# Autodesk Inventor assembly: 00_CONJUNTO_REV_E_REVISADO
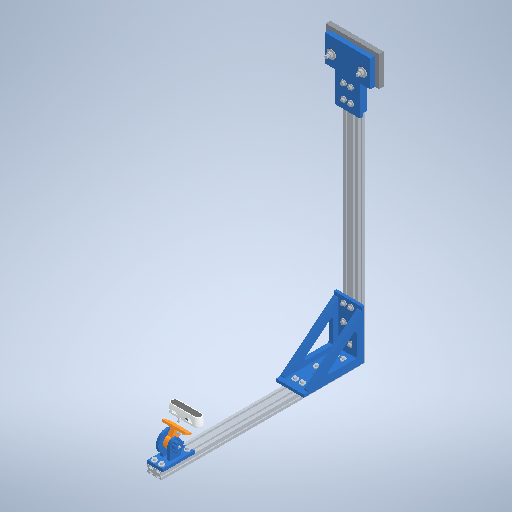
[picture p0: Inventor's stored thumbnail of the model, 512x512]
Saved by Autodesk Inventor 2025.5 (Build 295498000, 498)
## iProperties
Company: Open CASCADE
Created: 2026-10
Part Number: 00_CONJUNTO_REV_E_REVISADO
Description: Open CASCADE Model
Document SubType Name: Assembly
Designer: Luis M
Authority: Unknown
Sending System: Open CASCADE 7.9
Preprocessor: Open CASCADE STEP processor 7.9
Title: Open CASCADE Shape Model
Author: Author
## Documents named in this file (98)
- C:\Users\Luis M\Desktop\TESIS\CAD_TESIS\ACOPLE_CAMARA\ACOPLE_CAMARA.iam
- C:\Users\Luis M\Desktop\TESIS\CAD_TESIS\ACOPLE_CAMARA\IPT\COMPONENTES_IAM\perfil_horizontal_2040_700.ipt
- C:\Users\Luis M\Desktop\TESIS\CAD_TESIS\ACOPLE_CAMARA\IPT\COMPONENTES_IAM\perfil_vertical_2040_550.ipt
- C:\Users\Luis M\Desktop\TESIS\CAD_TESIS\ACOPLE_CAMARA\IPT\COMPONENTES_IAM\horquilla.ipt
- C:\Users\Luis M\Desktop\TESIS\CAD_TESIS\ACOPLE_CAMARA\IPT\COMPONENTES_IAM\placa_movil.ipt
- C:\Users\Luis M\Desktop\TESIS\CAD_TESIS\ACOPLE_CAMARA\IPT\COMPONENTES_IAM\pomo.ipt
- C:\Users\Luis M\Desktop\TESIS\CAD_TESIS\ACOPLE_CAMARA\IPT\COMPONENTES_IAM\adaptador_Jaco2_2040.ipt
- C:\Users\Luis M\Desktop\TESIS\CAD_TESIS\ACOPLE_CAMARA\IPT\COMPONENTES_IAM\base_Jaco2_BANDA_LOCAL_REFERENCIA.ipt
- C:\Users\Luis M\Desktop\TESIS\CAD_TESIS\ACOPLE_CAMARA\IPT\COMPONENTES_IAM\contraplaca_ACERO_1_5mm.ipt
- C:\Users\Luis M\Desktop\TESIS\CAD_TESIS\ACOPLE_CAMARA\IPT\COMPONENTES_IAM\pivote_M5x40.ipt
- C:\Users\Luis M\Desktop\TESIS\CAD_TESIS\ACOPLE_CAMARA\IPT\COMPONENTES_IAM\arandela_M5_-14.3.ipt
- C:\Users\Luis M\Desktop\TESIS\CAD_TESIS\ACOPLE_CAMARA\IPT\COMPONENTES_IAM\arandela_M5_13.3.ipt
- C:\Users\Luis M\Desktop\TESIS\CAD_TESIS\ACOPLE_CAMARA\IPT\COMPONENTES_IAM\tuerca_M5.ipt
- C:\Users\Luis M\Desktop\TESIS\CAD_TESIS\ACOPLE_CAMARA\IPT\COMPONENTES_IAM\M3x8_camara_-22.5.ipt
- C:\Users\Luis M\Desktop\TESIS\CAD_TESIS\ACOPLE_CAMARA\IPT\COMPONENTES_IAM\arandela_M3_-22.5.ipt
- C:\Users\Luis M\Desktop\TESIS\CAD_TESIS\ACOPLE_CAMARA\IPT\COMPONENTES_IAM\M3x8_camara_22.5.ipt
- C:\Users\Luis M\Desktop\TESIS\CAD_TESIS\ACOPLE_CAMARA\IPT\COMPONENTES_IAM\arandela_M3_22.5.ipt
- C:\Users\Luis M\Desktop\TESIS\CAD_TESIS\ACOPLE_CAMARA\IPT\COMPONENTES_IAM\M5x16_horquilla_-10_-36.0.ipt
- C:\Users\Luis M\Desktop\TESIS\CAD_TESIS\ACOPLE_CAMARA\IPT\COMPONENTES_IAM\arandela2mm_horquilla_-10_-36.0.ipt
- C:\Users\Luis M\Desktop\TESIS\CAD_TESIS\ACOPLE_CAMARA\IPT\COMPONENTES_IAM\T_horquilla_-10_-36.0.ipt
- C:\Users\Luis M\Desktop\TESIS\CAD_TESIS\ACOPLE_CAMARA\IPT\COMPONENTES_IAM\M5x16_horquilla_-10_36.0.ipt
- C:\Users\Luis M\Desktop\TESIS\CAD_TESIS\ACOPLE_CAMARA\IPT\COMPONENTES_IAM\arandela2mm_horquilla_-10_36.0.ipt
- C:\Users\Luis M\Desktop\TESIS\CAD_TESIS\ACOPLE_CAMARA\IPT\COMPONENTES_IAM\T_horquilla_-10_36.0.ipt
- C:\Users\Luis M\Desktop\TESIS\CAD_TESIS\ACOPLE_CAMARA\IPT\COMPONENTES_IAM\M5x16_collar_-10_630.ipt
- C:\Users\Luis M\Desktop\TESIS\CAD_TESIS\ACOPLE_CAMARA\IPT\COMPONENTES_IAM\arandela2mm_collar_-10_630.ipt
- C:\Users\Luis M\Desktop\TESIS\CAD_TESIS\ACOPLE_CAMARA\IPT\COMPONENTES_IAM\T_collar_-10_630.ipt
- C:\Users\Luis M\Desktop\TESIS\CAD_TESIS\ACOPLE_CAMARA\IPT\COMPONENTES_IAM\M5x16_collar_-10_670.ipt
- C:\Users\Luis M\Desktop\TESIS\CAD_TESIS\ACOPLE_CAMARA\IPT\COMPONENTES_IAM\arandela2mm_collar_-10_670.ipt
- C:\Users\Luis M\Desktop\TESIS\CAD_TESIS\ACOPLE_CAMARA\IPT\COMPONENTES_IAM\T_collar_-10_670.ipt
- C:\Users\Luis M\Desktop\TESIS\CAD_TESIS\ACOPLE_CAMARA\IPT\COMPONENTES_IAM\M5x16_horquilla_10_-36.0.ipt
- C:\Users\Luis M\Desktop\TESIS\CAD_TESIS\ACOPLE_CAMARA\IPT\COMPONENTES_IAM\arandela2mm_horquilla_10_-36.0.ipt
- C:\Users\Luis M\Desktop\TESIS\CAD_TESIS\ACOPLE_CAMARA\IPT\COMPONENTES_IAM\T_horquilla_10_-36.0.ipt
- C:\Users\Luis M\Desktop\TESIS\CAD_TESIS\ACOPLE_CAMARA\IPT\COMPONENTES_IAM\M5x16_horquilla_10_36.0.ipt
- C:\Users\Luis M\Desktop\TESIS\CAD_TESIS\ACOPLE_CAMARA\IPT\COMPONENTES_IAM\arandela2mm_horquilla_10_36.0.ipt
- C:\Users\Luis M\Desktop\TESIS\CAD_TESIS\ACOPLE_CAMARA\IPT\COMPONENTES_IAM\T_horquilla_10_36.0.ipt
- C:\Users\Luis M\Desktop\TESIS\CAD_TESIS\ACOPLE_CAMARA\IPT\COMPONENTES_IAM\M5x16_collar_10_630.ipt
- C:\Users\Luis M\Desktop\TESIS\CAD_TESIS\ACOPLE_CAMARA\IPT\COMPONENTES_IAM\arandela2mm_collar_10_630.ipt
- C:\Users\Luis M\Desktop\TESIS\CAD_TESIS\ACOPLE_CAMARA\IPT\COMPONENTES_IAM\T_collar_10_630.ipt
- C:\Users\Luis M\Desktop\TESIS\CAD_TESIS\ACOPLE_CAMARA\IPT\COMPONENTES_IAM\M5x16_collar_10_670.ipt
- C:\Users\Luis M\Desktop\TESIS\CAD_TESIS\ACOPLE_CAMARA\IPT\COMPONENTES_IAM\arandela2mm_collar_10_670.ipt
- C:\Users\Luis M\Desktop\TESIS\CAD_TESIS\ACOPLE_CAMARA\IPT\COMPONENTES_IAM\T_collar_10_670.ipt
- C:\Users\Luis M\Desktop\TESIS\CAD_TESIS\ACOPLE_CAMARA\IPT\COMPONENTES_IAM\11_acople_triangulado_derecho.ipt
- C:\Users\Luis M\Desktop\TESIS\CAD_TESIS\ACOPLE_CAMARA\IPT\COMPONENTES_IAM\12_acople_triangulado_izquierdo.ipt
- C:\Users\Luis M\Desktop\TESIS\CAD_TESIS\ACOPLE_CAMARA\IPT\COMPONENTES_IAM\M5x16_acople_v_-10_50.0.ipt
- C:\Users\Luis M\Desktop\TESIS\CAD_TESIS\ACOPLE_CAMARA\IPT\COMPONENTES_IAM\arandela_acople_v_-10_50.0.ipt
- C:\Users\Luis M\Desktop\TESIS\CAD_TESIS\ACOPLE_CAMARA\IPT\COMPONENTES_IAM\T_acople_v_-10_50.0.ipt
- C:\Users\Luis M\Desktop\TESIS\CAD_TESIS\ACOPLE_CAMARA\IPT\COMPONENTES_IAM\M5x16_acople_v_-10_105.0.ipt
- C:\Users\Luis M\Desktop\TESIS\CAD_TESIS\ACOPLE_CAMARA\IPT\COMPONENTES_IAM\arandela_acople_v_-10_105.0.ipt
- C:\Users\Luis M\Desktop\TESIS\CAD_TESIS\ACOPLE_CAMARA\IPT\COMPONENTES_IAM\T_acople_v_-10_105.0.ipt
- C:\Users\Luis M\Desktop\TESIS\CAD_TESIS\ACOPLE_CAMARA\IPT\COMPONENTES_IAM\M5x16_acople_v_-10_165.0.ipt
- C:\Users\Luis M\Desktop\TESIS\CAD_TESIS\ACOPLE_CAMARA\IPT\COMPONENTES_IAM\arandela_acople_v_-10_165.0.ipt
- C:\Users\Luis M\Desktop\TESIS\CAD_TESIS\ACOPLE_CAMARA\IPT\COMPONENTES_IAM\T_acople_v_-10_165.0.ipt
- C:\Users\Luis M\Desktop\TESIS\CAD_TESIS\ACOPLE_CAMARA\IPT\COMPONENTES_IAM\M5x16_acople_h_-10_45.0.ipt
- C:\Users\Luis M\Desktop\TESIS\CAD_TESIS\ACOPLE_CAMARA\IPT\COMPONENTES_IAM\arandela_acople_h_-10_45.0.ipt
- C:\Users\Luis M\Desktop\TESIS\CAD_TESIS\ACOPLE_CAMARA\IPT\COMPONENTES_IAM\T_acople_h_-10_45.0.ipt
- C:\Users\Luis M\Desktop\TESIS\CAD_TESIS\ACOPLE_CAMARA\IPT\COMPONENTES_IAM\M5x16_acople_h_-10_90.0.ipt
- C:\Users\Luis M\Desktop\TESIS\CAD_TESIS\ACOPLE_CAMARA\IPT\COMPONENTES_IAM\arandela_acople_h_-10_90.0.ipt
- C:\Users\Luis M\Desktop\TESIS\CAD_TESIS\ACOPLE_CAMARA\IPT\COMPONENTES_IAM\T_acople_h_-10_90.0.ipt
- C:\Users\Luis M\Desktop\TESIS\CAD_TESIS\ACOPLE_CAMARA\IPT\COMPONENTES_IAM\M5x16_acople_h_-10_135.0.ipt
- C:\Users\Luis M\Desktop\TESIS\CAD_TESIS\ACOPLE_CAMARA\IPT\COMPONENTES_IAM\arandela_acople_h_-10_135.0.ipt
- C:\Users\Luis M\Desktop\TESIS\CAD_TESIS\ACOPLE_CAMARA\IPT\COMPONENTES_IAM\T_acople_h_-10_135.0.ipt
- C:\Users\Luis M\Desktop\TESIS\CAD_TESIS\ACOPLE_CAMARA\IPT\COMPONENTES_IAM\M5x16_acople_v_10_50.0.ipt
- C:\Users\Luis M\Desktop\TESIS\CAD_TESIS\ACOPLE_CAMARA\IPT\COMPONENTES_IAM\arandela_acople_v_10_50.0.ipt
- C:\Users\Luis M\Desktop\TESIS\CAD_TESIS\ACOPLE_CAMARA\IPT\COMPONENTES_IAM\T_acople_v_10_50.0.ipt
- C:\Users\Luis M\Desktop\TESIS\CAD_TESIS\ACOPLE_CAMARA\IPT\COMPONENTES_IAM\M5x16_acople_v_10_105.0.ipt
- C:\Users\Luis M\Desktop\TESIS\CAD_TESIS\ACOPLE_CAMARA\IPT\COMPONENTES_IAM\arandela_acople_v_10_105.0.ipt
- C:\Users\Luis M\Desktop\TESIS\CAD_TESIS\ACOPLE_CAMARA\IPT\COMPONENTES_IAM\T_acople_v_10_105.0.ipt
- C:\Users\Luis M\Desktop\TESIS\CAD_TESIS\ACOPLE_CAMARA\IPT\COMPONENTES_IAM\M5x16_acople_v_10_165.0.ipt
- C:\Users\Luis M\Desktop\TESIS\CAD_TESIS\ACOPLE_CAMARA\IPT\COMPONENTES_IAM\arandela_acople_v_10_165.0.ipt
- C:\Users\Luis M\Desktop\TESIS\CAD_TESIS\ACOPLE_CAMARA\IPT\COMPONENTES_IAM\T_acople_v_10_165.0.ipt
- C:\Users\Luis M\Desktop\TESIS\CAD_TESIS\ACOPLE_CAMARA\IPT\COMPONENTES_IAM\M5x16_acople_h_10_45.0.ipt
- C:\Users\Luis M\Desktop\TESIS\CAD_TESIS\ACOPLE_CAMARA\IPT\COMPONENTES_IAM\arandela_acople_h_10_45.0.ipt
- C:\Users\Luis M\Desktop\TESIS\CAD_TESIS\ACOPLE_CAMARA\IPT\COMPONENTES_IAM\T_acople_h_10_45.0.ipt
- C:\Users\Luis M\Desktop\TESIS\CAD_TESIS\ACOPLE_CAMARA\IPT\COMPONENTES_IAM\M5x16_acople_h_10_90.0.ipt
- C:\Users\Luis M\Desktop\TESIS\CAD_TESIS\ACOPLE_CAMARA\IPT\COMPONENTES_IAM\arandela_acople_h_10_90.0.ipt
- C:\Users\Luis M\Desktop\TESIS\CAD_TESIS\ACOPLE_CAMARA\IPT\COMPONENTES_IAM\T_acople_h_10_90.0.ipt
- C:\Users\Luis M\Desktop\TESIS\CAD_TESIS\ACOPLE_CAMARA\IPT\COMPONENTES_IAM\M5x16_acople_h_10_135.0.ipt
- C:\Users\Luis M\Desktop\TESIS\CAD_TESIS\ACOPLE_CAMARA\IPT\COMPONENTES_IAM\arandela_acople_h_10_135.0.ipt
- C:\Users\Luis M\Desktop\TESIS\CAD_TESIS\ACOPLE_CAMARA\IPT\COMPONENTES_IAM\T_acople_h_10_135.0.ipt
- C:\Users\Luis M\Desktop\TESIS\CAD_TESIS\ACOPLE_CAMARA\IPT\COMPONENTES_IAM\DIN7991_M8x45_-43.5.ipt
- C:\Users\Luis M\Desktop\TESIS\CAD_TESIS\ACOPLE_CAMARA\IPT\COMPONENTES_IAM\arandela_M8_24x2_-43.5_15.ipt
- C:\Users\Luis M\Desktop\TESIS\CAD_TESIS\ACOPLE_CAMARA\IPT\COMPONENTES_IAM\arandela_M8_24x2_-43.5_29.5.ipt
- C:\Users\Luis M\Desktop\TESIS\CAD_TESIS\ACOPLE_CAMARA\IPT\COMPONENTES_IAM\casquillo_METAL_L12_5_-43.5.ipt
- C:\Users\Luis M\Desktop\TESIS\CAD_TESIS\ACOPLE_CAMARA\IPT\COMPONENTES_IAM\anillo_SILICONA_precarga_-43.5.ipt
- C:\Users\Luis M\Desktop\TESIS\CAD_TESIS\ACOPLE_CAMARA\IPT\COMPONENTES_IAM\centrador_PLA_-43.5.ipt
- C:\Users\Luis M\Desktop\TESIS\CAD_TESIS\ACOPLE_CAMARA\IPT\COMPONENTES_IAM\tuerca_M8_regular_-43.5.ipt
- C:\Users\Luis M\Desktop\TESIS\CAD_TESIS\ACOPLE_CAMARA\IPT\COMPONENTES_IAM\DIN7991_M8x45_43.5.ipt
- C:\Users\Luis M\Desktop\TESIS\CAD_TESIS\ACOPLE_CAMARA\IPT\COMPONENTES_IAM\arandela_M8_24x2_43.5_15.ipt
- C:\Users\Luis M\Desktop\TESIS\CAD_TESIS\ACOPLE_CAMARA\IPT\COMPONENTES_IAM\arandela_M8_24x2_43.5_29.5.ipt
- C:\Users\Luis M\Desktop\TESIS\CAD_TESIS\ACOPLE_CAMARA\IPT\COMPONENTES_IAM\casquillo_METAL_L12_5_43.5.ipt
- C:\Users\Luis M\Desktop\TESIS\CAD_TESIS\ACOPLE_CAMARA\IPT\COMPONENTES_IAM\anillo_SILICONA_precarga_43.5.ipt
- C:\Users\Luis M\Desktop\TESIS\CAD_TESIS\ACOPLE_CAMARA\IPT\COMPONENTES_IAM\centrador_PLA_43.5.ipt
- C:\Users\Luis M\Desktop\TESIS\CAD_TESIS\ACOPLE_CAMARA\IPT\COMPONENTES_IAM\tuerca_M8_regular_43.5.ipt
- C:\Users\Luis M\Desktop\TESIS\CAD_TESIS\ACOPLE_CAMARA\IPT\COMPONENTES_IAM\bloqueo_M3x30.ipt
- C:\Users\Luis M\Desktop\TESIS\CAD_TESIS\ACOPLE_CAMARA\IPT\COMPONENTES_IAM\arandela_bloqueo_M3_-14.3.ipt
- C:\Users\Luis M\Desktop\TESIS\CAD_TESIS\ACOPLE_CAMARA\IPT\COMPONENTES_IAM\arandela_bloqueo_M3_6.0.ipt
- C:\Users\Luis M\Desktop\TESIS\CAD_TESIS\ACOPLE_CAMARA\IPT\COMPONENTES_IAM\tuerca_bloqueo_M3_Nyloc.ipt
- C:\Users\Luis M\Desktop\TESIS\CAD_TESIS\ACOPLE_CAMARA\INTEL_REALSENSE_D435I.ipt
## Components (97 placed, 97 different names)
1. Perfil V-Slot 2040 x 700 mm - horizontal (referencia)
2. Perfil V-Slot 2040 x 550 mm - vertical (referencia)
3. horquilla_3
4. placa_movil_4
5. pomo_5
6. adaptador_Jaco2_2040_6
7. Base robot Jaco2 - banda local de referencia
8. contraplaca_ACERO_1_5mm_8
9. Pivote tornillo M5 x 40 mm
10. Arandela M5 - pivote - -14.3
11. Arandela M5 - pivote - 13.3
12. Tuerca hexagonal M5 - pivote
13. Tornillo M3 x 8 mm - camara - -22.5 — Coincidencia:1
14. Arandela M3 - camara - -22.5
15. Tornillo M3 x 8 mm - camara - 22.5
16. Arandela M3 - camara - 22.5
17. Tornillo M5 x 16 mm - horquilla -10 -36.0
18. Arandela M5 Ø15 x Ø5.3 x 2 mm - horquilla -10 -36.0
19. Tuerca T M5 para perfil V-Slot 2040 - horquilla -10 -36.0
20. Tornillo M5 x 16 mm - horquilla -10 36.0
21. Arandela M5 Ø15 x Ø5.3 x 2 mm - horquilla -10 36.0
22. Tuerca T M5 para perfil V-Slot 2040 - horquilla -10 36.0
23. Tornillo M5 x 16 mm - soporte del perfil -10 630
24. Arandela M5 Ø15 x Ø5.3 x 2 mm - soporte del perfil -10 630
25. Tuerca T M5 para perfil V-Slot 2040 - soporte del perfil -10 630
26. Tornillo M5 x 16 mm - soporte del perfil -10 670
27. Arandela M5 Ø15 x Ø5.3 x 2 mm - soporte del perfil -10 670
28. Tuerca T M5 para perfil V-Slot 2040 - soporte del perfil -10 670
29. Tornillo M5 x 16 mm - horquilla 10 -36.0
30. Arandela M5 Ø15 x Ø5.3 x 2 mm - horquilla 10 -36.0
31. Tuerca T M5 para perfil V-Slot 2040 - horquilla 10 -36.0
32. Tornillo M5 x 16 mm - horquilla 10 36.0
33. Arandela M5 Ø15 x Ø5.3 x 2 mm - horquilla 10 36.0
34. Tuerca T M5 para perfil V-Slot 2040 - horquilla 10 36.0
35. Tornillo M5 x 16 mm - soporte del perfil 10 630
36. Arandela M5 Ø15 x Ø5.3 x 2 mm - soporte del perfil 10 630
37. Tuerca T M5 para perfil V-Slot 2040 - soporte del perfil 10 630
38. Tornillo M5 x 16 mm - soporte del perfil 10 670
39. Arandela M5 Ø15 x Ø5.3 x 2 mm - soporte del perfil 10 670
40. Tuerca T M5 para perfil V-Slot 2040 - soporte del perfil 10 670
41. 11_acople_triangulado_derecho_45
42. 12_acople_triangulado_izquierdo_46
43. Tornillo M5 x 16 mm - cartabon vertical -10 50.0
44. Arandela M5 - cartabon - v -10 50.0
45. Tuerca T M5 para perfil V-Slot 2040 - cartabon vertical -10 50.0
46. Tornillo M5 x 16 mm - cartabon vertical -10 105.0
47. Arandela M5 - cartabon - v -10 105.0
48. Tuerca T M5 para perfil V-Slot 2040 - cartabon vertical -10 105.0
49. Tornillo M5 x 16 mm - cartabon vertical -10 165.0
50. Arandela M5 - cartabon - v -10 165.0
51. Tuerca T M5 para perfil V-Slot 2040 - cartabon vertical -10 165.0
52. Tornillo M5 x 16 mm - cartabon horizontal -10 45.0
53. Arandela M5 - cartabon - h -10 45.0
54. Tuerca T M5 para perfil V-Slot 2040 - cartabon horizontal -10 45.0
55. Tornillo M5 x 16 mm - cartabon horizontal -10 90.0
56. Arandela M5 - cartabon - h -10 90.0
57. Tuerca T M5 para perfil V-Slot 2040 - cartabon horizontal -10 90.0
58. Tornillo M5 x 16 mm - cartabon horizontal -10 135.0
59. Arandela M5 - cartabon - h -10 135.0
60. Tuerca T M5 para perfil V-Slot 2040 - cartabon horizontal -10 135.0
61. Tornillo M5 x 16 mm - cartabon vertical 10 50.0
62. Arandela M5 - cartabon - v 10 50.0
63. Tuerca T M5 para perfil V-Slot 2040 - cartabon vertical 10 50.0
64. Tornillo M5 x 16 mm - cartabon vertical 10 105.0
65. Arandela M5 - cartabon - v 10 105.0
66. Tuerca T M5 para perfil V-Slot 2040 - cartabon vertical 10 105.0
67. Tornillo M5 x 16 mm - cartabon vertical 10 165.0
68. Arandela M5 - cartabon - v 10 165.0
69. Tuerca T M5 para perfil V-Slot 2040 - cartabon vertical 10 165.0
70. Tornillo M5 x 16 mm - cartabon horizontal 10 45.0
71. Arandela M5 - cartabon - h 10 45.0
72. Tuerca T M5 para perfil V-Slot 2040 - cartabon horizontal 10 45.0
73. Tornillo M5 x 16 mm - cartabon horizontal 10 90.0
74. Arandela M5 - cartabon - h 10 90.0
75. Tuerca T M5 para perfil V-Slot 2040 - cartabon horizontal 10 90.0
76. Tornillo M5 x 16 mm - cartabon horizontal 10 135.0
77. Arandela M5 - cartabon - h 10 135.0
78. Tuerca T M5 para perfil V-Slot 2040 - cartabon horizontal 10 135.0
79. Tornillo avellanado DIN 7991 M8 x 45 mm - -43.5
80. Arandela M8 Ø24 x Ø8.4 x 2 mm - -43.5 15
81. Arandela M8 Ø24 x Ø8.4 x 2 mm - -43.5 29.5
82. casquillo_METAL_L12_5_-43.5_86
83. Anillo de silicona Ø24 x Ø14.5 x 2 mm - -43.5
84. centrador_PLA_-43.5_88
85. Tuerca hexagonal M8 AF13 - -43.5
86. Tornillo avellanado DIN 7991 M8 x 45 mm - 43.5
87. Arandela M8 Ø24 x Ø8.4 x 2 mm - 43.5 15
88. Arandela M8 Ø24 x Ø8.4 x 2 mm - 43.5 29.5
89. casquillo_METAL_L12_5_43.5_93
90. Anillo de silicona Ø24 x Ø14.5 x 2 mm - 43.5
91. centrador_PLA_43.5_95
92. Tuerca hexagonal M8 AF13 - 43.5
93. Tornillo M3 x 30 mm - bloqueo angular
94. Arandela M3 - bloqueo angular - -14.3
95. Arandela M3 - bloqueo angular - 6.0
96. Tuerca autofrenante M3 - bloqueo angular
97. Camara Intel RealSense D435i — Coincidencia:1
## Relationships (1: Mate 1)
- Coincidencia:1 [Mate]: Tornillo M3 x 8 mm - camara - -22.5 ↔ Camara Intel RealSense D435i
